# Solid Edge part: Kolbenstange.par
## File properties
Username: ahadarics
Dokumentum tartalom típus: 0
Author: ahadarics
Last saved by: ahadarics
Revision: 82
Sűrűség: 0,000 kg/m^3
Pontosság: 0,990
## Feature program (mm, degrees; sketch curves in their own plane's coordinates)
base feature "unnamed BaseFeature 1"
thread "unnamed Thread 1"
chamfer "Letörés_1" setback 0.7
sketch for "Kihúzás_1" plane through (54.25, 0, 0) normal (1, 0, 0) x-axis (0, -1, 0)
  circle centre (0, 0) radius 10
extrude "Kihúzás_1" add finite 26.5 along -normal
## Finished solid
Body 1: solid body, 13 faces, 23 edges, 12 vertices.
  Faces by surface: plane 9, cylinder 3, cone 1
  Edges by curve: line 12, circle 11
Bounding box of the edges (mm): 248.000 x 20.000 x 20.000, from (-193.75, -10, -10) to (54.25, 10, 10).
Cylindrical faces by radius (mm): R4 x2, R10 x1
Conical faces (half-angle, radius in mm at the cone's reference point): 45 deg R3.3 x1
Planar faces by outward normal: +x 3, +z 1, -x 4, -z 1
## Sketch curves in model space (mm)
circle centre (54.25, 0, 0) radius 10
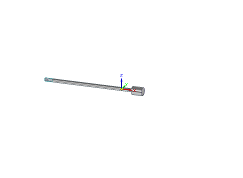
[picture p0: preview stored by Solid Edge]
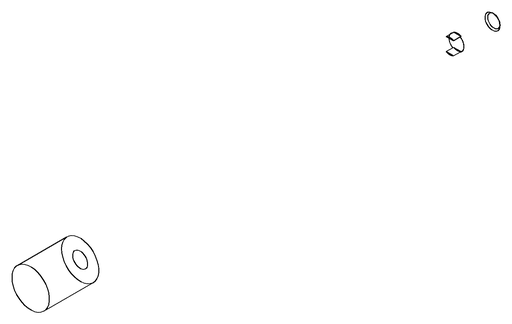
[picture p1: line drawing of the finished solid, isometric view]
